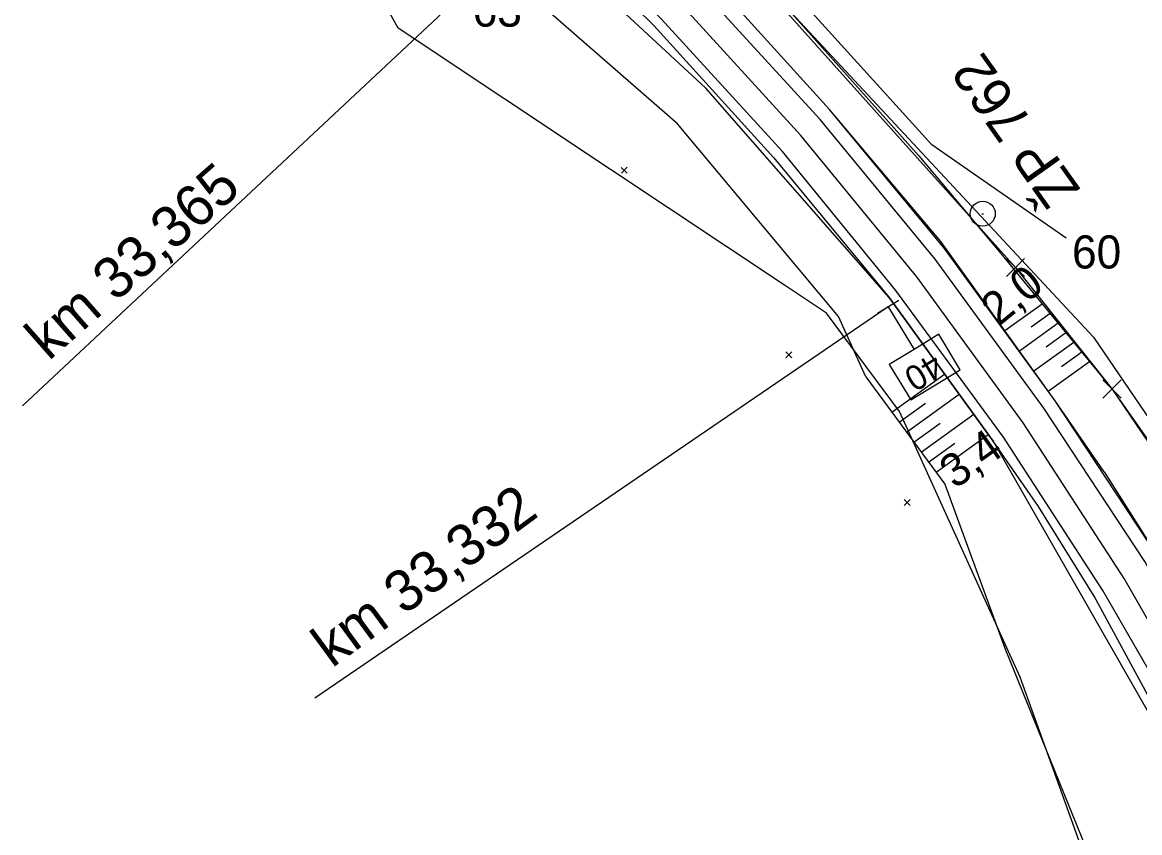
# Model space of a CAD drawing. Extents: x -805011 to -803920, y -1150790 to -1150234.
# Drawn here: x -804242.8 to -804175.3, y -1150583.2 to -1150534.3 of the extents above; entities that cross this region are included whole.
import ezdxf

# ---------------------------------------------------------------- set-up
doc = ezdxf.new("R2010")
doc.units = 0
for name, color, linetype in [('0381KM032-037P - Vrstva 1', 7, 'Continuous'), ('0381KM032-037P - Vrstva 4', 7, 'Continuous'), ('0381KM032-037P - Vrstva 48', 7, 'Continuous'), ('0381KM032-037P - Vrstva 49', 7, 'Continuous'), ('0381KM032-037P - Vrstva 5', 7, 'Continuous'), ('0381KM032-037P - Vrstva 6', 7, 'Continuous'), ('Default', 7, 'Continuous'), ('hran DP - hran DP', 7, 'Continuous'), ('PSR_C2_2_Lomove_body_Vimperk - Vrstva 60', 7, 'Continuous'), ('PSR_C2_2_trasa_Vimperk - Kabelová trasa', 7, 'Continuous'), ('vyt_sit - ohrožené', 7, 'Continuous')]:
    doc.layers.add(name, color=color, linetype=linetype)

msp = doc.modelspace()

# ---------------------------------------------------------------- linework, layer by layer
at = {"layer": '0381KM032-037P - Vrstva 1'}
msp.add_lwpolyline([(-804170.822, -1150577.298), (-804176.258, -1150567.853), (-804182.371, -1150558.448), (-804188.8, -1150549.629), (-804195.802, -1150541.086), (-804203.2, -1150532.984), (-804210.727, -1150525.566), (-804219.762, -1150517.68), (-804222.979, -1150515.095)], dxfattribs=at)
at = {"layer": '0381KM032-037P - Vrstva 4'}
for points in [[(-804187.111, -1150547.908), (-804194.057, -1150539.524), (-804201.534, -1150531.257), (-804209.073, -1150523.878), (-804215.386, -1150518.402), (-804217.606, -1150517.412)], [(-804187.677, -1150548.561), (-804194.635, -1150540.132), (-804202.18, -1150531.866), (-804209.673, -1150524.484), (-804217.606, -1150517.412)], [(-804190.063, -1150550.442), (-804196.905, -1150542.065), (-804204.246, -1150534.035), (-804211.902, -1150526.624), (-804219.035, -1150520.275), (-804218.825, -1150521.196), (-804212.362, -1150526.896), (-804204.686, -1150534.438)], [(-804204.686, -1150534.438), (-804197.425, -1150542.443), (-804190.457, -1150550.873)], [(-804155.31, -1150604.52), (-804159.649, -1150594.756), (-804164.129, -1150585.172), (-804168.865, -1150576.083), (-804174.28, -1150566.446), (-804180.439, -1150557.113), (-804187.111, -1150547.908)], [(-804155.958, -1150604.81), (-804160.35, -1150595.071), (-804164.873, -1150585.497), (-804169.431, -1150576.623), (-804175.01, -1150566.818), (-804181.125, -1150557.549), (-804187.677, -1150548.561)], [(-804159.667, -1150606.247), (-804163.987, -1150596.782), (-804168.29, -1150587.201), (-804172.877, -1150578.495), (-804178.084, -1150568.907), (-804181.433, -1150563.503), (-804184.179, -1150559.55), (-804190.457, -1150550.873)], [(-804158.943, -1150605.891), (-804163.074, -1150596.409), (-804167.658, -1150586.765), (-804172.113, -1150577.988), (-804177.545, -1150568.561), (-804183.558, -1150559.317), (-804190.063, -1150550.442)]]:
    msp.add_lwpolyline(points, dxfattribs=at)
at = {"layer": '0381KM032-037P - Vrstva 48'}
for p, q in [((-804181.215, -1150551.268), (-804183.472, -1150552.889)), ((-804180.738, -1150551.849), (-804181.886, -1150552.674)), ((-804180.261, -1150552.43), (-804182.597, -1150554.107)), ((-804179.307, -1150553.592), (-804181.722, -1150555.326)), ((-804179.784, -1150553.011), (-804180.972, -1150553.864)), ((-804178.83, -1150554.173), (-804180.057, -1150555.054)), ((-804178.353, -1150554.754), (-804180.847, -1150556.544)), ((-804190.305, -1150557.806), (-804187.112, -1150555.496)), ((-804189.413, -1150559.013), (-804186.233, -1150556.711)), ((-804189.859, -1150558.409), (-804188.266, -1150557.257)), ((-804188.522, -1150560.219), (-804185.354, -1150557.927)), ((-804188.968, -1150559.616), (-804187.381, -1150558.468)), ((-804188.077, -1150560.823), (-804186.495, -1150559.679)), ((-804187.631, -1150561.426), (-804184.474, -1150559.142))]:
    msp.add_line(p, q, dxfattribs=at)
at = {"layer": '0381KM032-037P - Vrstva 49'}
for p, q in [((-804206.644, -1150543.012), (-804206.29, -1150543.364)), ((-804206.291, -1150543.011), (-804206.643, -1150543.365)), ((-804196.699, -1150554.165), (-804196.345, -1150554.517)), ((-804196.346, -1150554.164), (-804196.698, -1150554.518)), ((-804189.547, -1150563.081), (-804189.193, -1150563.433)), ((-804189.194, -1150563.08), (-804189.546, -1150563.434))]:
    msp.add_line(p, q, dxfattribs=at)
for points in [[(-804179.775, -1150547.299), (-804187.894, -1150541.654), (-804195.903, -1150532.804), (-804214.14, -1150512.69)], [(-804216.26, -1150515.03), (-804196.494, -1150533.54), (-804188.661, -1150542.31), (-804183.721, -1150548.216), (-804176.998, -1150556.404), (-804165.664, -1150573.065), (-804155.488, -1150590.499), (-804146.445, -1150604.861), (-804136.373, -1150622.314), (-804131.913, -1150629.82), (-804122.713, -1150645.636), (-804115.713, -1150666.787), (-804102.893, -1150677.063), (-804092.506, -1150687.924), (-804076.709, -1150692.971), (-804062.718, -1150701.966), (-804052.08, -1150706.52)], [(-804194.057, -1150539.524), (-804201.534, -1150531.257), (-804209.073, -1150523.878), (-804215.386, -1150518.402), (-804219.465, -1150515.789)], [(-804190.457, -1150550.873), (-804201.544, -1150538.223), (-804219.6, -1150521.51)], [(-804191.878, -1150555.675), (-804193.532, -1150552.027), (-804203.252, -1150540.379), (-804221.09, -1150524.83)], [(-804177.463, -1150561.393), (-804180.439, -1150557.113), (-804187.342, -1150547.499), (-804194.057, -1150539.524)], [(-804190.457, -1150550.873), (-804184.179, -1150559.55), (-804171.889, -1150581.005)], [(-804191.878, -1150555.675), (-804187.094, -1150562.154), (-804183.466, -1150572.059), (-804177.466, -1150586.829), (-804171.323, -1150602.684), (-804162.19, -1150629.627), (-804127.409, -1150694.052), (-804117.854, -1150694.755), (-804107.487, -1150702.042), (-804103.027, -1150704.725), (-804070.42, -1150728.33), (-804053.81, -1150732.63), (-804001.622, -1150732.392)], [(-804177.463, -1150561.393), (-804174.28, -1150566.446), (-804168.865, -1150576.083), (-804164.129, -1150585.172), (-804156.198, -1150601.212), (-804142.816, -1150631.284), (-804134.642, -1150648.129), (-804125.753, -1150662.222), (-804122.657, -1150666.252)]]:
    msp.add_lwpolyline(points, dxfattribs=at)
at = {"layer": '0381KM032-037P - Vrstva 5'}
for p, q in [((-804190.519, -1150551.446), (-804225.169, -1150575.08)), ((-804189.878, -1150551.056), (-804191.16, -1150551.836))]:
    msp.add_line(p, q, dxfattribs=at)
msp.add_lwpolyline([(-804190.519, -1150551.446), (-804188.959, -1150554.008), (-804190.454, -1150554.918), (-804189.154, -1150557.054), (-804186.164, -1150555.234), (-804187.464, -1150553.098), (-804188.959, -1150554.008)], dxfattribs=at)
at = {"layer": '0381KM032-037P - Vrstva 6'}
msp.add_line((-804212.64, -1150529.17), (-804242.831, -1150557.407), dxfattribs=at)
at = {"layer": 'hran DP - hran DP'}
for p, q in [((-804220.13, -1150534.61), (-804223.47, -1150528.51)), ((-804196.65, -1150533.37), (-804178.11, -1150553.27)), ((-804207.3, -1150543.14), (-804220.13, -1150534.61)), ((-804196.79, -1150550.13), (-804207.3, -1150543.14)), ((-804194.25, -1150551.81), (-804196.79, -1150550.13)), ((-804189.84, -1150557.76), (-804194.25, -1150551.81)), ((-804178.11, -1150553.27), (-804167.37, -1150569.11)), ((-804182.55, -1150573.8), (-804189.84, -1150557.76)), ((-804170.78, -1150606.46), (-804182.55, -1150573.8))]:
    msp.add_line(p, q, dxfattribs=at)
at = {"layer": 'PSR_C2_2_Lomove_body_Vimperk - Vrstva 60'}
for p, q in [((-804183.383, -1150549.613), (-804182.283, -1150548.513)), ((-804182.283, -1150549.613), (-804183.383, -1150548.513)), ((-804177.548, -1150556.954), (-804176.448, -1150555.854)), ((-804176.448, -1150556.954), (-804177.548, -1150555.854))]:
    msp.add_line(p, q, dxfattribs=at)
at = {"layer": 'PSR_C2_2_trasa_Vimperk - Kabelová trasa'}
msp.add_lwpolyline([(-804211.944, -1150528.206), (-804207.531, -1150523.605), (-804196.767, -1150533.523), (-804182.833, -1150549.063), (-804176.998, -1150556.404), (-804170.601, -1150565.498), (-804165.463, -1150573.105), (-804159.32, -1150583.604), (-804148.335, -1150601.453), (-804139.822, -1150616.034), (-804133.21, -1150627.359), (-804121.848, -1150646.675), (-804112.033, -1150660.854), (-804099.514, -1150673.08)], dxfattribs=at)
at = {"layer": 'vyt_sit - ohrožené'}
msp.add_line((-804184.857, -1150545.814), (-804184.757, -1150545.814), dxfattribs=at)
msp.add_circle((-804184.807, -1150545.814), 0.756, dxfattribs=at)

# ---------------------------------------------------------------- texts
at = {"layer": '0381KM032-037P - Vrstva 48'}
for s, rotation, p in [('2,0', 39.38872, (-804183.859, -1150552.669)), ('3,4', 35.33808, (-804186.488, -1150562.479))]:
    msp.add_text(s, height=2, rotation=rotation, dxfattribs=at).set_placement(p)
at = {"layer": '0381KM032-037P - Vrstva 5'}
for s, height, rotation, p in [('40', 1.5, 211.33438, (-804187.789, -1150554.174)), ('km 33,332', 2.5, 36.33438, (-804224.126, -1150573.284))]:
    msp.add_text(s, height=height, rotation=rotation, dxfattribs=at).set_placement(p)
at = {"layer": '0381KM032-037P - Vrstva 6'}
msp.add_text('km 33,365', height=2.5, rotation=41.34441, dxfattribs=at).set_placement((-804241.239, -1150554.742))
at = {"layer": 'Default'}
for s, p in [('63', (-804215.627, -1150534.515)), ('60', (-804179.415, -1150549.122))]:
    msp.add_text(s, height=2, dxfattribs=at).set_placement(p)
at = {"layer": 'vyt_sit - ohrožené'}
msp.add_text('ŽP 762', height=2.4, rotation=125.43858, dxfattribs=at).set_placement((-804178.853, -1150544.364))

doc.saveas('drawing.dxf')
